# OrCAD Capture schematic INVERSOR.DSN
size A
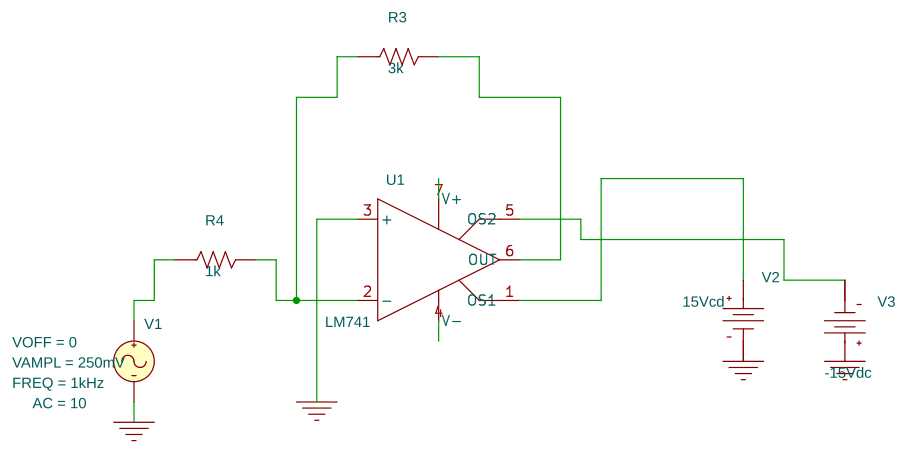
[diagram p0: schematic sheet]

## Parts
R3  3k  [RC05]
R4  1k  [RC05]
U1  LM741  [DIP.100/8/W.300/L.450]
V1  VSIN
V2  VDC
V3  VDC

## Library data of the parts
R3 R4 = R
U1 = LM741_v2
V1 = VSIN: AC: 10; FREQ: 1kHz; VAMPL: 250mV; VOFF: 0
V2 = VDC: DC: 15Vcd
V3 = VDC: DC: -15Vdc

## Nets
0: U1.3(+) V1.2(-) V2.1(-) V3.0(+)
N00183: R4.1 V1.1(+)
N00202: R3.1 R4.2 U1.2(-)
N04852: R3.2 U1.6(OUT)
N05102: U1.1(OS1) V2.0(+)
N05114: U1.5(OS2) V3.1(-)

Not connected (* = marked no-connect by the designer): U1 4(V-) 7(V+)
